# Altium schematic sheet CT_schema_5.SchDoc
size 577 x 363 mm
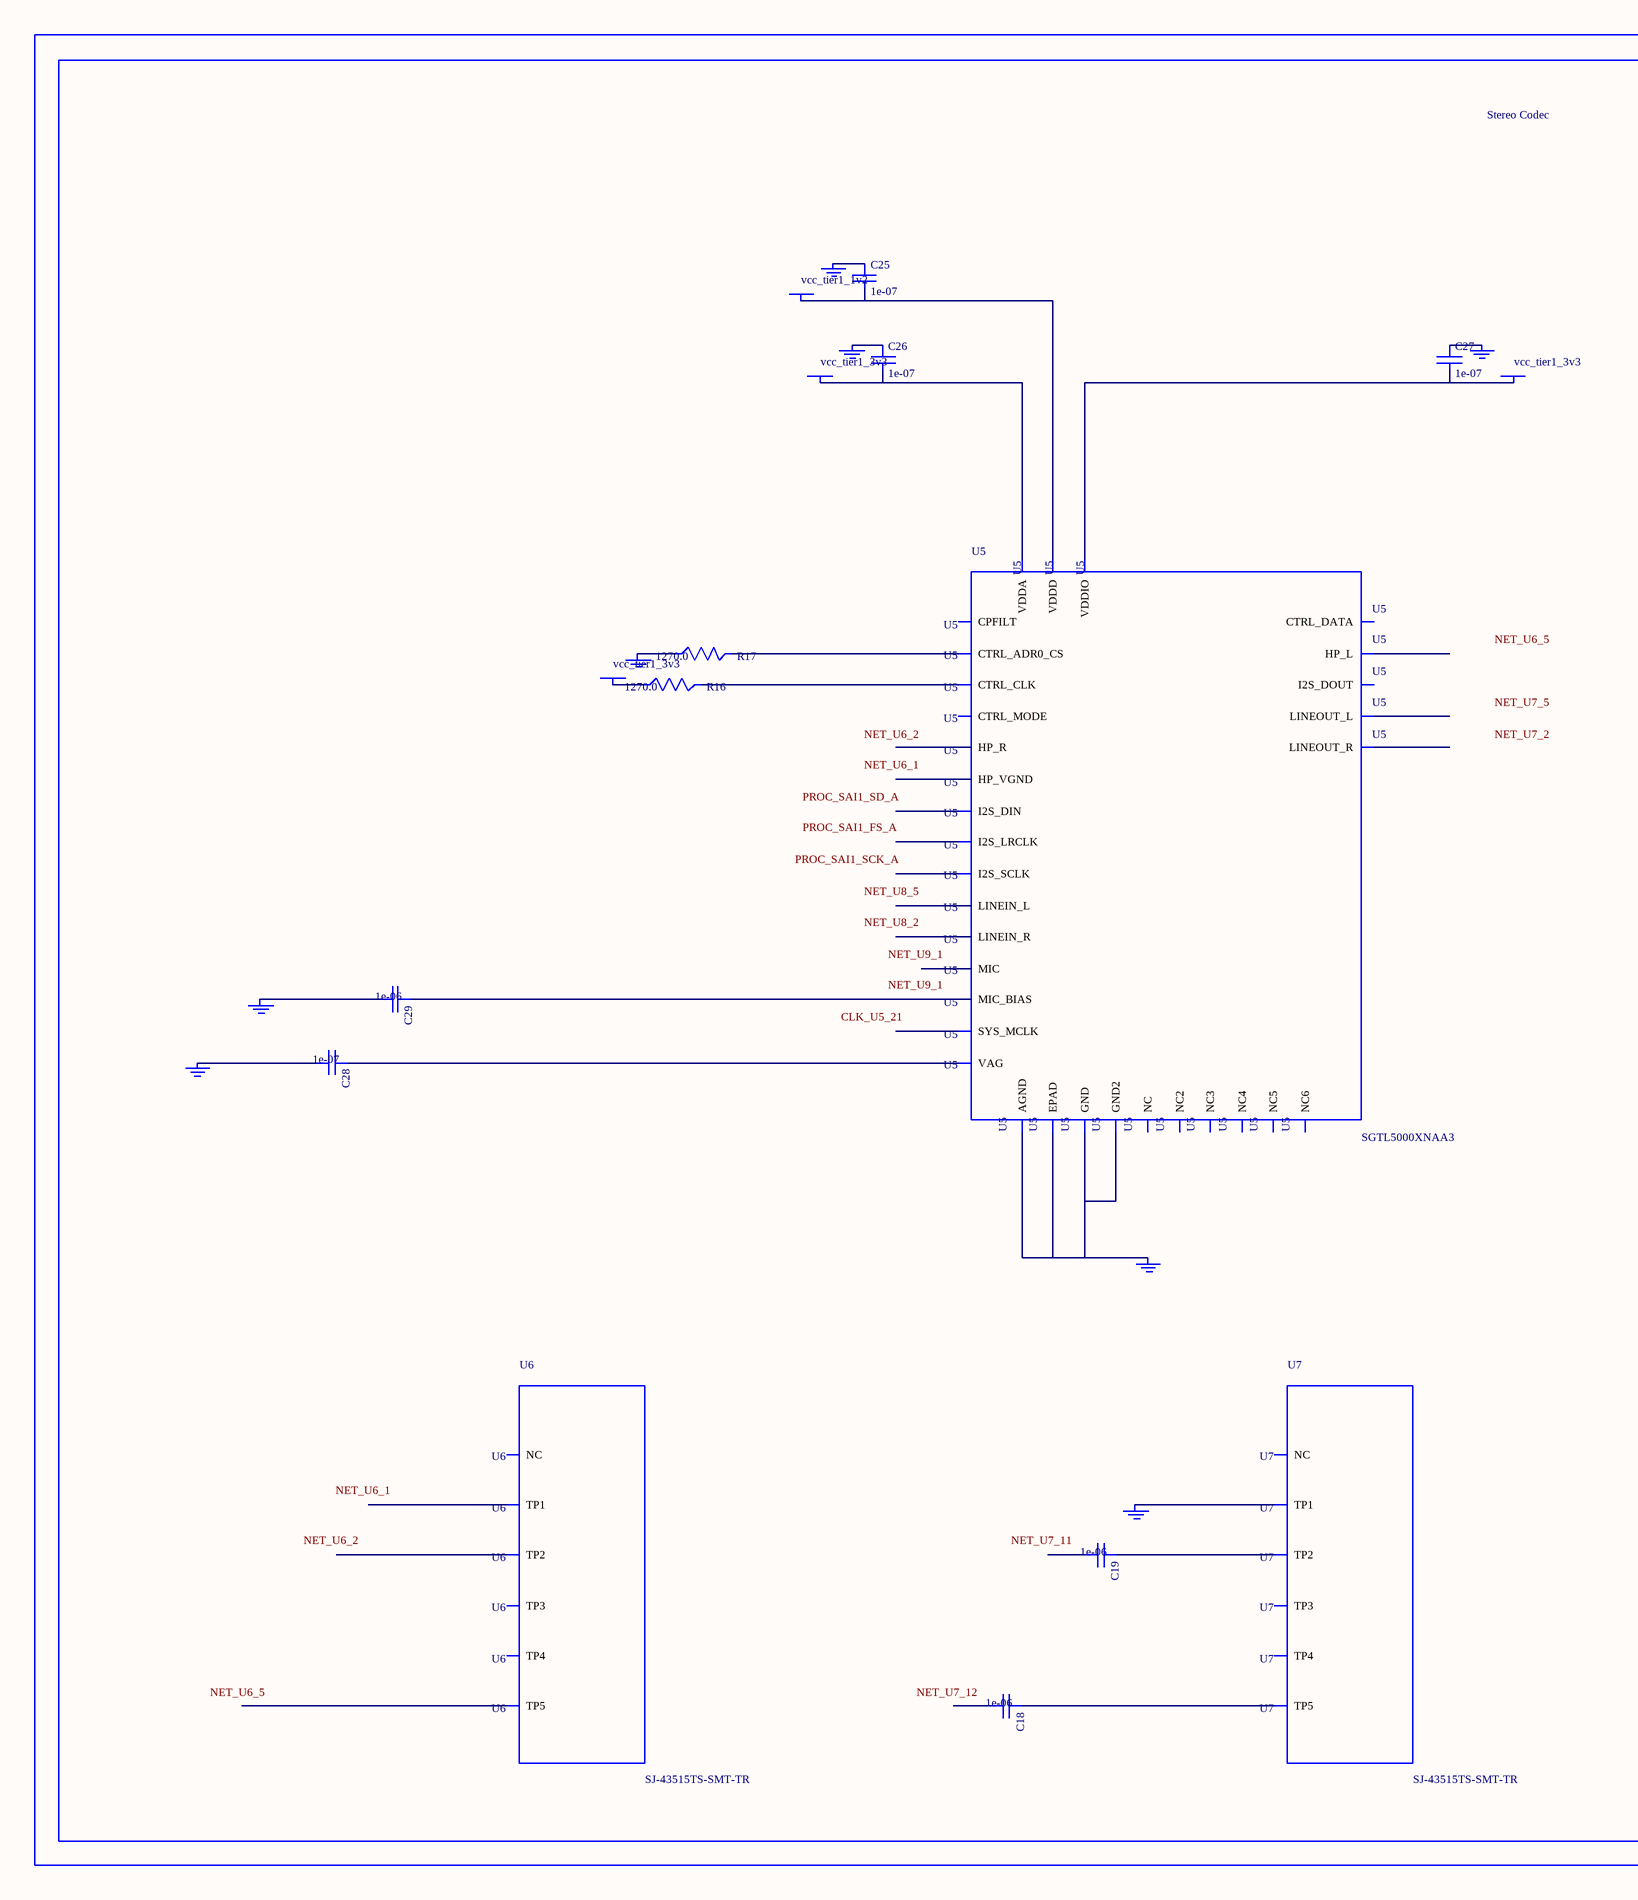
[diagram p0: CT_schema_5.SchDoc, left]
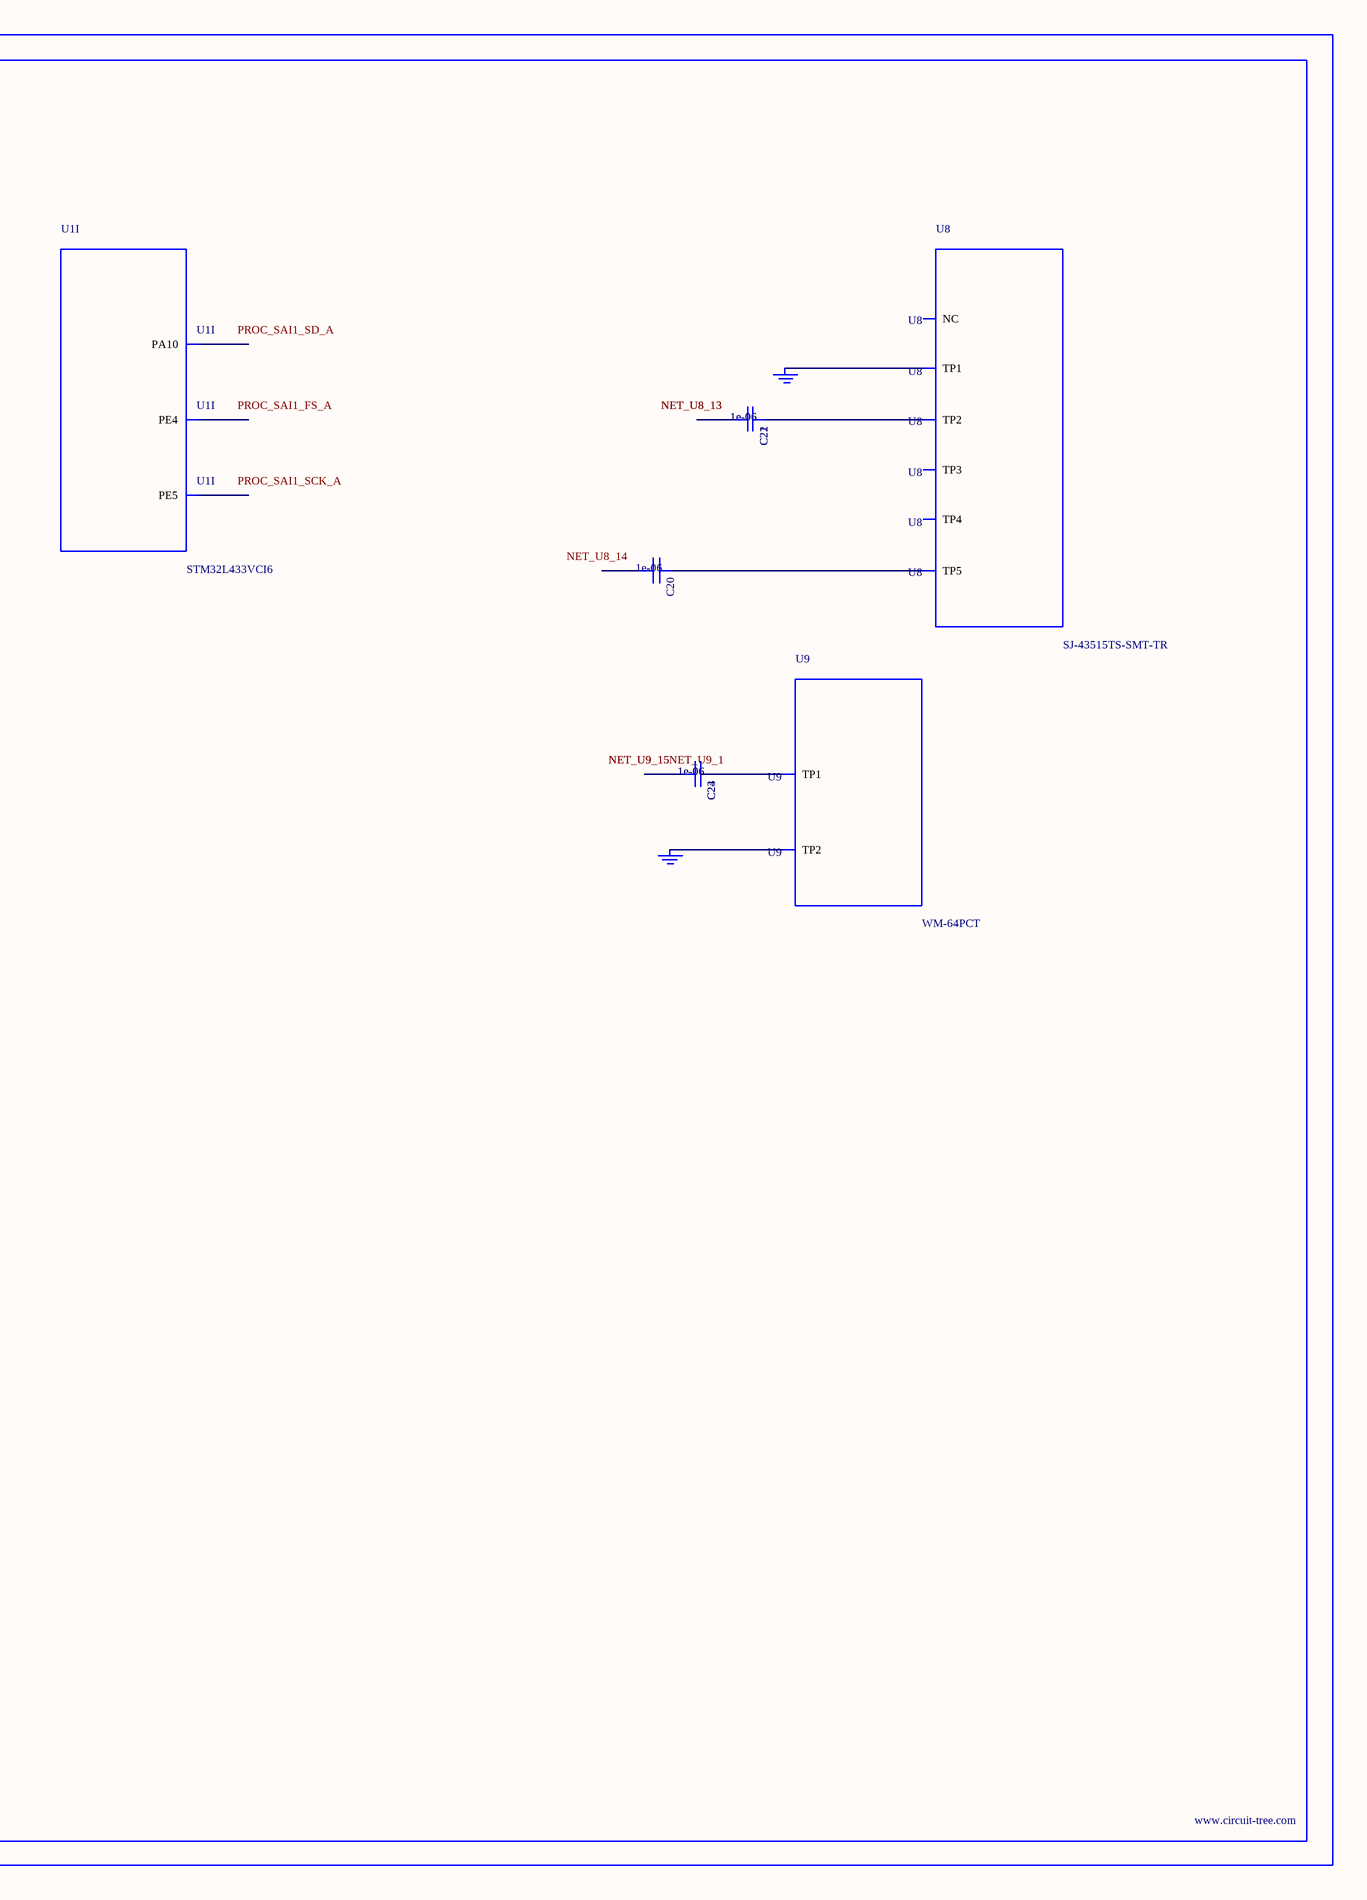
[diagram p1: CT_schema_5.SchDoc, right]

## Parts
BORDER4  (no value)
C18  1e-06  [C0603]
C19  1e-06  [C0603]
C20  1e-06  [C0603]
C21  1e-06  [C0603]
C22  1e-06  [C0603]
C23  1e-06  [C0603]
C24  1e-06  [C0603]
C25  1e-07  [C0402]
C26  1e-07  [C0402]
C27  1e-07  [C0402]
C28  1e-07  [C0402]
C29  1e-06  [C0603]
GND_INSTANCE_4_0  (no value)
GND_INSTANCE_4_1  (no value)
GND_INSTANCE_4_2  (no value)
GND_INSTANCE_4_3  (no value)
GND_INSTANCE_4_4  (no value)
GND_INSTANCE_4_5  (no value)
GND_INSTANCE_4_6  (no value)
GND_INSTANCE_4_7  (no value)
GND_INSTANCE_4_8  (no value)
GND_INSTANCE_4_9  (no value)
GND_INSTANCE_4_10  (no value)
POWER_INSTANCE_4_0  vcc_tier1_3v3
POWER_INSTANCE_4_1  vcc_tier1_3v3
POWER_INSTANCE_4_2  vcc_tier1_3v3
POWER_INSTANCE_4_3  vcc_tier1_1v2
R16  1270.0  [R0603]
R17  1270.0  [R0603]
U1  STM32L433VCI6  [UFBGA100]  (part I of 11)
U5  SGTL5000XNAA3  [QFN-32]
U6  SJ-43515TS-SMT-TR  [SJ-43515TS-SMT-TR]
U7  SJ-43515TS-SMT-TR  [SJ-43515TS-SMT-TR]
U8  SJ-43515TS-SMT-TR  [SJ-43515TS-SMT-TR]
U9  WM-64PCT  [WM-64PC]

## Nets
NetC18_1: C18.1 U7.5(TP5)
NetC19_1: C19.1 U7.2(TP2)
NetC20_1: C20.1 U8.5(TP5)
NetC21_1: C21.1 C22.1 U8.2(TP2)
NetC21_2: C21.2 C22.2
NetC23_1: C23.1 C24.1 U9.1(TP1)
NetC23_2: C23.2 C24.2
NetC25_1: C25.1 GND_INSTANCE_4_5.0(GND)
NetC25_2: C25.2 POWER_INSTANCE_4_3.0(PWR) U5.30(VDDD)
NetC26_1: C26.1 GND_INSTANCE_4_1.0(GND)
NetC26_2: C26.2 POWER_INSTANCE_4_0.0(PWR) U5.5(VDDA)
NetC27_1: C27.1 GND_INSTANCE_4_4.0(GND)
NetC27_2: C27.2 POWER_INSTANCE_4_1.0(PWR) U5.20(VDDIO)
NetC28_1: C28.1 U5.10(VAG)
NetC28_2: C28.2 GND_INSTANCE_4_2.0(GND)
NetC29_1: C29.1 U5.16(MIC_BIAS)
NetC29_2: C29.2 GND_INSTANCE_4_3.0(GND)
NetGND_INSTANCE_4_0_0: GND_INSTANCE_4_0.0(GND) U5.1(GND) U5.3(GND2) U5.7(AGND) U5.EXP(EPAD)
NetGND_INSTANCE_4_6_0: GND_INSTANCE_4_6.0(GND) R17.1
NetGND_INSTANCE_4_7_0: GND_INSTANCE_4_7.0(GND) U7.1(TP1)
NetGND_INSTANCE_4_8_0: GND_INSTANCE_4_8.0(GND) GND_INSTANCE_4_9.0(GND) U8.1(TP1)
NetGND_INSTANCE_4_10_0: GND_INSTANCE_4_10.0(GND) U9.2(TP2)
NetPOWER_INSTANCE_4_2_0: POWER_INSTANCE_4_2.0(PWR) R16.1
NetR16_2: R16.2 U5.29(CTRL_CLK)
NetR17_2: R17.2 U5.31(CTRL_ADR0_CS)

Not connected (* = marked no-connect by the designer): C18 2; C19 2; C20 2; U1 B1(PE4) C2(PE5) C12(PA10); U5 2(HP_R) 4(HP_VGND) 6(HP_L) 8(NC) 9(NC2) 11(LINEOUT_R) 12(LINEOUT_L) 13(LINEIN_R) 14(LINEIN_L) 15(MIC) 17(NC3) 18(CPFILT) 19(NC4) 21(SYS_MCLK) 22(NC5) 23(I2S_LRCLK) 24(I2S_SCLK) 25(I2S_DOUT) 26(I2S_DIN) 27(CTRL_DATA) 28(NC6) 32(CTRL_MODE); U6 1(TP1) 2(TP2) 3(TP3) 4(TP4) 5(TP5) 6(NC); U7 3(TP3) 4(TP4) 6(NC); U8 3(TP3) 4(TP4) 6(NC)

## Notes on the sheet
- Labels drawn without touching a wire or pin: CLK_U5_21, NET_U6_1, NET_U6_2, NET_U6_5, NET_U7_2, NET_U7_5, NET_U7_11, NET_U7_12, NET_U8_2, NET_U8_5, NET_U8_14, NET_U9_1, PROC_SAI1_FS_A, PROC_SAI1_SCK_A, PROC_SAI1_SD_A

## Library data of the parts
BORDER4 = BORDER_PAGE4
C18-C24 C29 = C0603C105K3RACTU
C25-C28 = C0402C104K3RACTU
GND_INSTANCE_4_0-GND_INSTANCE_4_10 = GND
POWER_INSTANCE_4_0-POWER_INSTANCE_4_3 = PWR
R16 R17 = RC0603FR-071K27L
